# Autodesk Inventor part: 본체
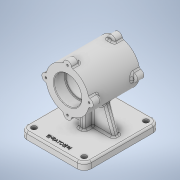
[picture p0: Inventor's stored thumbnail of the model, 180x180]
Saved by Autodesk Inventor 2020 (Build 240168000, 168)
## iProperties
Created: 2022-11
Part Number: 본체
Material: 일반
Document SubType Name: Modeling
Designer: owner
Density: 1 g/cm^3
Appearance: 기본값
Mass: 450.145 g
Surface Area: 796.917 cm^2
Volume: 450.145 cm^3
Author: owner
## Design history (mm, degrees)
sketch "스케치1"
  geometry: L1 (0, 0)-(87, 0); L2 (0, 37)-(0, 23.5); L3 (0, 23.5)-(19, 23.5); L4 (19, 23.5)-(19, 21); L5 (19, 21)-(68, 21); L6 (68, 21)-(68, 23.5); L7 (68, 23.5)-(87, 23.5); L8 (87, 23.5)-(87, 37); L9 (87, 37)-(0, 37); 2 further points
  constraints: 18 end point, 7 perpendicular, 2 midpoint, 2 vertical alignment, 1 horizontal, 1 vertical
  dimensions: "d0" = 87 distance of L1.start L1.end; "d1" = 47 diameter of L7 L1; "d2" = 47 diameter of L3 L1; "d3" = 42 diameter of L5 L1; "d4" = 19 distance of L2.end L3.end; "d5" = 19 distance of L6.end L7.end; "d6" = 74 diameter of L9 L1
revolve "회전1" sketch "스케치1" stored, may be unused: angle "d7" = 90 deg
node "작업 평면1"
sketch "스케치2"
  geometry: L1 (26.5, -55)-(-103.5, -55); L2 (-103.5, -55)-(-103.5, 55); L3 (-103.5, 55)-(26.5, 55); L4 (26.5, 55)-(26.5, -55); L5 (26.5, -55)-(-103.5, 55); L6 (-103.5, -55)-(26.5, 55); L7 (0, 37)-(-87, 37) reference; 4 further points
  constraints: 12 end point, 4 midpoint, 2 parallel, 1 horizontal, 1 horizontal alignment, 1 perpendicular
  dimensions: "d9" = 130 distance of L2.end L3.end; "d10" = 110 distance of L1.end L2.end; "d11" = 70 distance from line of L4 point (-43.5, 37)
extrude "돌출1" join sketch "스케치2" distance "d12" = 12; taper "d13" = 0 deg
fillet "모깎기1" dims "d14" = 12
sketch "스케치3"
  geometry: A1 r 12 centre (-14.5, -43) between (-26.5, -43) and (-14.5, -55) reference; 2 further points
  constraints: 1 coincident
hole "구멍1" sketch "스케치3" at (-14.5, -43) diameter "d15" = 9; stored, may be unused: countersink angle "d19" = 90 deg, drill point angle "d21" = 118 deg; dims "d16" = 6, "d17" = 4, "d18" = 2, "d20" = 8
node "작업 평면2"
node "작업 평면3"
sketch "스케치5"
  geometry: L1 (-70, -43)-(-70, 43) reference; L2 (-26.964, -25.336)-(-70, -41); L3 (-70, 43)-(-70, -43) reference; L4 (-70, 41)-(-26.964, 25.336); L5 (-70, -55)-(-82, -55) reference; L6 (-70, -43)-(-70, -55) reference; L7 (-82, 55)-(-70, 55) reference; A1 r 37 centre (0, 0) between (-26.964, -25.336) and (-26.964, 25.336) reference; 3 further points
  constraints: 4 end point, 2 point on circle, 2 point on line, 1 equal length
  dimensions: "d26" = 14 distance from line of L5 L2.end; "d27" = 110 deg angle of L6 L2; "d28" = 14 distance from line of L7 L4.start
extrude "돌출2" join sketch "스케치5" stored distance "d29" = 10; taper "d30" = 0 deg
sketch "스케치6"
  geometry: L1 (-14.5, -70)-(91.5, -70) reference; L2 (23.5, -70)-(23.5, -51.412); L3 (43.5, 60.8)-(43.5, -105.8) reference; 1 further point
  constraints: 2 end point, 1 point on line, 1 vertical
  dimensions: "d31" = 20 distance between parallel lines of L2 L3
feature "리브1" sketch "스케치6" dims "d32" = 1, "d33" = 10, "d34" = 0, "d35" = 0, "d36" = 1, "d37" = 1
sketch "스케치7"
  geometry: A1 r 37 centre (0, 0) between (0, 37) and (-6.969, 36.338) reference; A2 r 7 centre (0, 37) between (6.969, 36.338) and (-6.969, 36.338); 1 further point
  constraints: 5 point on circle, 1 centre point, 1 vertical alignment
  dimensions: "d38" = 14 diameter of A2
extrude "돌출3" join sketch "스케치7" distance "d39" = 14; taper "d40" = 0 deg
sketch "스케치8"
  geometry: A1 r 37 centre (0, -37) between (-6.969, -0.662) and (6.969, -0.662) reference; A2 r 37 centre (0, -37) between (6.969, -0.662) and (-6.969, -0.662) reference; 3 further points
  constraints: 1 coincident, 1 point on circle
hole "구멍2" sketch "스케치8" at (0, 0) diameter "d41" = 3.242; stored, may be unused: countersink angle "d45" = 90 deg, drill point angle "d47" = 118 deg; dims "d42" = 8, "d43" = 4, "d44" = 2, "d46" = 10
fillet "모깎기2" dims "d51" = 3
fillet "모깎기3" dims "d52" = 3
fillet "모깎기4" dims "d53" = 3
fillet "모깎기5" dims "d54" = 3
fillet "모깎기6" dims "d55" = 3
fillet "모깎기7" dims "d56" = 1
chamfer "모따기1" distance "d57" = 1; stored, may be unused: second distance "d58" = 2, angle "d59" = 45 deg
sketch "스케치9"
  geometry: L1 (43.5, 77)-(43.5, -77) reference; L2 (-14.5, -55)-(91.5, -55) reference; 2 further points
  constraints: 1 other
  dimensions: "d60" = 58 distance from line of point (-14.5, 0) L1; "d61" = 55 distance from line of L2 point (-14.5, 0)
feature "엠보싱1" sketch "스케치9" dims "d9" = 130, "d10" = 110, "d11" = 70, "d62" = 0.5, "d63" = 0
node "솔리드1"
mirror "미러1"
mirror "미러2"
mirror "미러3"
pattern_circular "원형 패턴1" dims angle "d49" = 360 deg
mirror "미러4"
feature "A9D066F2-1C7D-4E18-AEED-F7BC21143FA4" dims "d15" = 9, "d16" = 6, "d17" = 4, "d18" = 2, "d19" = 90 deg, "d20" = 8, "d21" = 118 deg
other parameters: "d8" = -82, "d25" = 43.5
